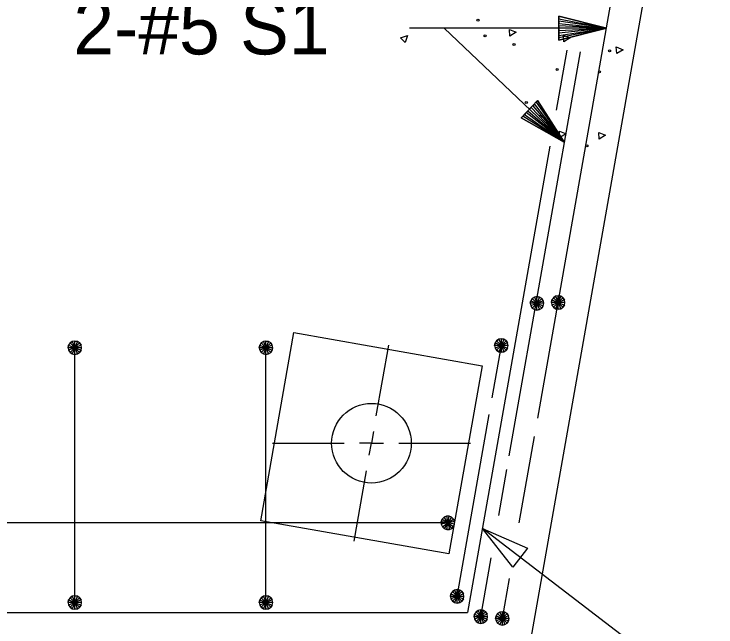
# Model space of a CAD drawing. Extents: x -408 to -23, y -15 to 117.
# Drawn here: x -81.977 to -80.141, y 60.353 to 61.957 of the extents above; entities that cross this region are included whole.
import ezdxf

# ---------------------------------------------------------------- set-up
doc = ezdxf.new("R2010")
doc.units = 0
for name, color, linetype in [('Arrowhead Terminators CELL', 7, 'Continuous'), ('Dimension Lines', 7, 'Continuous'), ('Rebar Lines', 7, 'Continuous'), ('Sup Concrete Girder Lines', 7, 'Continuous'), ('Sup Cored Slab Unit', 7, 'Continuous'), ('Text', 7, 'Continuous')]:
    doc.layers.add(name, color=color, linetype=linetype)

msp = doc.modelspace()

# ---------------------------------------------------------------- linework, layer by layer
at = {"layer": 'Arrowhead Terminators CELL'}
msp.add_lwpolyline([(-80.7517, 60.6104), (-80.6335, 60.5591), (-80.6716, 60.5095)], close=True, dxfattribs=at)
at = {"layer": 'Dimension Lines'}
for p, q in [((-80.4271, 61.9193), (-80.8512, 61.9194)), ((-81.0293, 60.9054), (-80.9967, 61.09)), ((-81.301, 60.8335), (-81.1135, 60.8335)), ((-80.9704, 60.8335), (-80.7829, 60.8335)), ((-81.0872, 60.5769), (-81.0546, 60.7615))]:
    msp.add_line(p, q, dxfattribs=at)
for points in [[(-80.5521, 61.9193), (-80.5521, 61.9131), (-80.4271, 61.9193), (-80.5521, 61.9068), (-80.5521, 61.9006), (-80.4271, 61.9193), (-80.5521, 61.8943), (-80.5521, 61.8881), (-80.4271, 61.9193), (-80.5521, 61.9506), (-80.5521, 61.9443), (-80.4271, 61.9193), (-80.5521, 61.9381), (-80.5521, 61.9318), (-80.4271, 61.9193), (-80.5521, 61.9256), (-80.5521, 61.8881), (-80.5521, 61.9506), (-80.4271, 61.9193), (-80.5521, 61.8881)], [(-80.5381, 61.6214), (-80.8512, 61.9194), (-80.9421, 61.9194)], [(-80.6287, 61.7076), (-80.633, 61.7031), (-80.5381, 61.6214), (-80.6373, 61.6985), (-80.6416, 61.694), (-80.5381, 61.6214), (-80.6459, 61.6895), (-80.6502, 61.685), (-80.5381, 61.6214), (-80.6071, 61.7302), (-80.6114, 61.7257), (-80.5381, 61.6214), (-80.6158, 61.7212), (-80.62, 61.7166), (-80.5381, 61.6214), (-80.6244, 61.7121), (-80.6502, 61.685), (-80.6071, 61.7302), (-80.5381, 61.6214), (-80.6502, 61.685)], [(-81.0365, 60.8644), (-81.0419, 60.8335), (-81.0734, 60.8336)], [(-81.0475, 60.8026), (-81.0419, 60.8335), (-81.0105, 60.8333)], [(-80.1546, 60.2743), (-80.3138, 60.2743), (-80.7517, 60.6104)]]:
    msp.add_lwpolyline(points, dxfattribs=at)
at = {"layer": 'Rebar Lines'}
for p, q in [((-80.4532, 61.7715), (-80.362, 62.2887)), ((-80.6815, 60.8001), (-80.4951, 61.8574)), ((-80.531, 61.8622), (-80.5587, 61.7052)), ((-80.6069, 60.8995), (-80.4532, 61.7715)), ((-80.5753, 61.611), (-80.7904, 60.3908)), ((-81.8177, 60.4168), (-81.8177, 61.0834)), ((-81.3177, 60.4168), (-81.3177, 61.0834)), ((-80.7262, 60.9519), (-80.702, 61.0893)), ((-80.8177, 60.4328), (-80.7338, 60.9087)), ((-80.6554, 60.6248), (-80.6154, 60.8515)), ((-80.709, 60.6441), (-80.6877, 60.7647)), ((-80.8419, 60.6251), (-83.5294, 60.6251)), ((-80.7556, 60.3796), (-80.7285, 60.5335)), ((-80.6994, 60.3751), (-80.681, 60.4791)), ((-82.1544, 60.3908), (-80.7904, 60.3908))]:
    msp.add_line(p, q, dxfattribs=at)
for points in [[(-80.5913, 61.1996), (-80.5926, 61.2063), (-80.5964, 61.2121), (-80.6021, 61.2159), (-80.6089, 61.2172), (-80.6156, 61.2159), (-80.6213, 61.2121), (-80.6251, 61.2064), (-80.6265, 61.1996), (-80.6251, 61.1929), (-80.6213, 61.1872), (-80.6157, 61.1833), (-80.6089, 61.182), (-80.6021, 61.1833), (-80.5964, 61.1871), (-80.5926, 61.1928), (-80.5913, 61.1996), (-80.6089, 61.1996), (-80.6265, 61.1996), (-80.6251, 61.2064), (-80.6089, 61.1996), (-80.6213, 61.2121), (-80.6156, 61.2159), (-80.6089, 61.1996), (-80.6089, 61.2172), (-80.6021, 61.2159), (-80.6089, 61.1996), (-80.5964, 61.2121), (-80.5926, 61.2063), (-80.6089, 61.1996), (-80.5926, 61.1928), (-80.5964, 61.1871), (-80.6089, 61.1996), (-80.6021, 61.1833), (-80.6089, 61.182), (-80.6089, 61.1996), (-80.6157, 61.1833), (-80.6213, 61.1872), (-80.6089, 61.1996), (-80.6251, 61.1929)], [(-80.536, 61.2018), (-80.5373, 61.2085), (-80.5411, 61.2142), (-80.5469, 61.2181), (-80.5536, 61.2194), (-80.5603, 61.2181), (-80.5661, 61.2142), (-80.5699, 61.2085), (-80.5712, 61.2018), (-80.5699, 61.195), (-80.5661, 61.1893), (-80.5604, 61.1855), (-80.5536, 61.1841), (-80.5469, 61.1855), (-80.5412, 61.1893), (-80.5373, 61.195), (-80.536, 61.2018), (-80.5536, 61.2018), (-80.5712, 61.2018), (-80.5699, 61.2085), (-80.5536, 61.2018), (-80.5661, 61.2142), (-80.5603, 61.2181), (-80.5536, 61.2018), (-80.5536, 61.2194), (-80.5469, 61.2181), (-80.5536, 61.2018), (-80.5411, 61.2142), (-80.5373, 61.2085), (-80.5536, 61.2018), (-80.5373, 61.195), (-80.5412, 61.1893), (-80.5536, 61.2018), (-80.5469, 61.1855), (-80.5536, 61.1841), (-80.5536, 61.2018), (-80.5604, 61.1855), (-80.5661, 61.1893), (-80.5536, 61.2018), (-80.5699, 61.195)], [(-81.8001, 61.0834), (-81.8014, 61.0901), (-81.8052, 61.0959), (-81.811, 61.0997), (-81.8177, 61.101), (-81.8245, 61.0997), (-81.8302, 61.0959), (-81.834, 61.0902), (-81.8353, 61.0834), (-81.834, 61.0767), (-81.8302, 61.071), (-81.8245, 61.0671), (-81.8177, 61.0658), (-81.811, 61.0671), (-81.8053, 61.0709), (-81.8014, 61.0766), (-81.8001, 61.0834), (-81.8177, 61.0834), (-81.8353, 61.0834), (-81.834, 61.0902), (-81.8177, 61.0834), (-81.8302, 61.0959), (-81.8245, 61.0997), (-81.8177, 61.0834), (-81.8177, 61.101), (-81.811, 61.0997), (-81.8177, 61.0834), (-81.8052, 61.0959), (-81.8014, 61.0901), (-81.8177, 61.0834), (-81.8014, 61.0766), (-81.8053, 61.0709), (-81.8177, 61.0834), (-81.811, 61.0671), (-81.8177, 61.0658), (-81.8177, 61.0834), (-81.8245, 61.0671), (-81.8302, 61.071), (-81.8177, 61.0834), (-81.834, 61.0767)], [(-81.3001, 61.0834), (-81.3014, 61.0901), (-81.3052, 61.0959), (-81.311, 61.0997), (-81.3177, 61.101), (-81.3245, 61.0997), (-81.3302, 61.0959), (-81.334, 61.0902), (-81.3353, 61.0834), (-81.334, 61.0767), (-81.3302, 61.071), (-81.3245, 61.0671), (-81.3177, 61.0658), (-81.311, 61.0671), (-81.3053, 61.0709), (-81.3014, 61.0766), (-81.3001, 61.0834), (-81.3177, 61.0834), (-81.3353, 61.0834), (-81.334, 61.0902), (-81.3177, 61.0834), (-81.3302, 61.0959), (-81.3245, 61.0997), (-81.3177, 61.0834), (-81.3177, 61.101), (-81.311, 61.0997), (-81.3177, 61.0834), (-81.3052, 61.0959), (-81.3014, 61.0901), (-81.3177, 61.0834), (-81.3014, 61.0766), (-81.3053, 61.0709), (-81.3177, 61.0834), (-81.311, 61.0671), (-81.3177, 61.0658), (-81.3177, 61.0834), (-81.3245, 61.0671), (-81.3302, 61.071), (-81.3177, 61.0834), (-81.334, 61.0767)], [(-80.6844, 61.0893), (-80.6857, 61.096), (-80.6895, 61.1017), (-80.6952, 61.1056), (-80.702, 61.1069), (-80.7087, 61.1056), (-80.7144, 61.1017), (-80.7182, 61.0961), (-80.7196, 61.0893), (-80.7182, 61.0826), (-80.7144, 61.0768), (-80.7087, 61.073), (-80.702, 61.0716), (-80.6952, 61.073), (-80.6895, 61.0768), (-80.6857, 61.0825), (-80.6844, 61.0893), (-80.702, 61.0893), (-80.7196, 61.0893), (-80.7182, 61.0961), (-80.702, 61.0893), (-80.7144, 61.1017), (-80.7087, 61.1056), (-80.702, 61.0893), (-80.702, 61.1069), (-80.6952, 61.1056), (-80.702, 61.0893), (-80.6895, 61.1017), (-80.6857, 61.096), (-80.702, 61.0893), (-80.6857, 61.0825), (-80.6895, 61.0768), (-80.702, 61.0893), (-80.6952, 61.073), (-80.702, 61.0716), (-80.702, 61.0893), (-80.7087, 61.073), (-80.7144, 61.0768), (-80.702, 61.0893), (-80.7182, 61.0826)], [(-80.8247, 60.6221), (-80.8248, 60.6289), (-80.8275, 60.6352), (-80.8325, 60.64), (-80.8389, 60.6425), (-80.8457, 60.6424), (-80.852, 60.6396), (-80.8568, 60.6346), (-80.8593, 60.6282), (-80.8591, 60.6213), (-80.8564, 60.615), (-80.8515, 60.6102), (-80.845, 60.6077), (-80.8381, 60.6079), (-80.8319, 60.6107), (-80.8271, 60.6157), (-80.8247, 60.6221), (-80.8419, 60.6251), (-80.8593, 60.6282), (-80.8568, 60.6346), (-80.8419, 60.6251), (-80.852, 60.6396), (-80.8457, 60.6424), (-80.8419, 60.6251), (-80.8389, 60.6425), (-80.8325, 60.64), (-80.8419, 60.6251), (-80.8275, 60.6352), (-80.8248, 60.6289), (-80.8419, 60.6251), (-80.8271, 60.6157), (-80.8319, 60.6107), (-80.8419, 60.6251), (-80.8381, 60.6079), (-80.845, 60.6077), (-80.8419, 60.6251), (-80.8515, 60.6102), (-80.8564, 60.615), (-80.8419, 60.6251), (-80.8591, 60.6213)], [(-80.8001, 60.4328), (-80.8014, 60.4395), (-80.8052, 60.4452), (-80.811, 60.4491), (-80.8177, 60.4504), (-80.8245, 60.4491), (-80.8302, 60.4452), (-80.834, 60.4396), (-80.8353, 60.4328), (-80.834, 60.4261), (-80.8302, 60.4203), (-80.8245, 60.4165), (-80.8177, 60.4151), (-80.811, 60.4165), (-80.8053, 60.4203), (-80.8014, 60.426), (-80.8001, 60.4328), (-80.8177, 60.4328), (-80.8353, 60.4328), (-80.834, 60.4396), (-80.8177, 60.4328), (-80.8302, 60.4452), (-80.8245, 60.4491), (-80.8177, 60.4328), (-80.8177, 60.4504), (-80.811, 60.4491), (-80.8177, 60.4328), (-80.8052, 60.4452), (-80.8014, 60.4395), (-80.8177, 60.4328), (-80.8014, 60.426), (-80.8053, 60.4203), (-80.8177, 60.4328), (-80.811, 60.4165), (-80.8177, 60.4151), (-80.8177, 60.4328), (-80.8245, 60.4165), (-80.8302, 60.4203), (-80.8177, 60.4328), (-80.834, 60.4261)], [(-81.8001, 60.4168), (-81.8014, 60.4235), (-81.8052, 60.4292), (-81.811, 60.4331), (-81.8177, 60.4344), (-81.8245, 60.4331), (-81.8302, 60.4292), (-81.834, 60.4235), (-81.8353, 60.4168), (-81.834, 60.41), (-81.8302, 60.4043), (-81.8245, 60.4005), (-81.8177, 60.3991), (-81.811, 60.4005), (-81.8053, 60.4043), (-81.8014, 60.41), (-81.8001, 60.4168), (-81.8177, 60.4168), (-81.8353, 60.4168), (-81.834, 60.4235), (-81.8177, 60.4168), (-81.8302, 60.4292), (-81.8245, 60.4331), (-81.8177, 60.4168), (-81.8177, 60.4344), (-81.811, 60.4331), (-81.8177, 60.4168), (-81.8052, 60.4292), (-81.8014, 60.4235), (-81.8177, 60.4168), (-81.8014, 60.41), (-81.8053, 60.4043), (-81.8177, 60.4168), (-81.811, 60.4005), (-81.8177, 60.3991), (-81.8177, 60.4168), (-81.8245, 60.4005), (-81.8302, 60.4043), (-81.8177, 60.4168), (-81.834, 60.41)], [(-81.3001, 60.4168), (-81.3014, 60.4235), (-81.3052, 60.4292), (-81.311, 60.4331), (-81.3177, 60.4344), (-81.3245, 60.4331), (-81.3302, 60.4292), (-81.334, 60.4235), (-81.3353, 60.4168), (-81.334, 60.41), (-81.3302, 60.4043), (-81.3245, 60.4005), (-81.3177, 60.3991), (-81.311, 60.4005), (-81.3053, 60.4043), (-81.3014, 60.41), (-81.3001, 60.4168), (-81.3177, 60.4168), (-81.3353, 60.4168), (-81.334, 60.4235), (-81.3177, 60.4168), (-81.3302, 60.4292), (-81.3245, 60.4331), (-81.3177, 60.4168), (-81.3177, 60.4344), (-81.311, 60.4331), (-81.3177, 60.4168), (-81.3052, 60.4292), (-81.3014, 60.4235), (-81.3177, 60.4168), (-81.3014, 60.41), (-81.3053, 60.4043), (-81.3177, 60.4168), (-81.311, 60.4005), (-81.3177, 60.3991), (-81.3177, 60.4168), (-81.3245, 60.4005), (-81.3302, 60.4043), (-81.3177, 60.4168), (-81.334, 60.41)], [(-80.738, 60.3796), (-80.7393, 60.3863), (-80.7431, 60.392), (-80.7488, 60.3959), (-80.7556, 60.3972), (-80.7623, 60.3959), (-80.7681, 60.392), (-80.7719, 60.3863), (-80.7732, 60.3796), (-80.7719, 60.3728), (-80.7681, 60.3671), (-80.7624, 60.3633), (-80.7556, 60.3619), (-80.7488, 60.3633), (-80.7432, 60.3671), (-80.7393, 60.3728), (-80.738, 60.3796), (-80.7556, 60.3796), (-80.7732, 60.3796), (-80.7719, 60.3863), (-80.7556, 60.3796), (-80.7681, 60.392), (-80.7623, 60.3959), (-80.7556, 60.3796), (-80.7556, 60.3972), (-80.7488, 60.3959), (-80.7556, 60.3796), (-80.7431, 60.392), (-80.7393, 60.3863), (-80.7556, 60.3796), (-80.7393, 60.3728), (-80.7432, 60.3671), (-80.7556, 60.3796), (-80.7488, 60.3633), (-80.7556, 60.3619), (-80.7556, 60.3796), (-80.7624, 60.3633), (-80.7681, 60.3671), (-80.7556, 60.3796), (-80.7719, 60.3728)], [(-80.6818, 60.3751), (-80.6831, 60.3819), (-80.6869, 60.3876), (-80.6926, 60.3914), (-80.6994, 60.3927), (-80.7061, 60.3914), (-80.7118, 60.3876), (-80.7156, 60.3819), (-80.717, 60.3751), (-80.7156, 60.3684), (-80.7118, 60.3627), (-80.7061, 60.3588), (-80.6994, 60.3575), (-80.6926, 60.3588), (-80.6869, 60.3626), (-80.6831, 60.3684), (-80.6818, 60.3751), (-80.6994, 60.3751), (-80.717, 60.3751), (-80.7156, 60.3819), (-80.6994, 60.3751), (-80.7118, 60.3876), (-80.7061, 60.3914), (-80.6994, 60.3751), (-80.6994, 60.3927), (-80.6926, 60.3914), (-80.6994, 60.3751), (-80.6869, 60.3876), (-80.6831, 60.3819), (-80.6994, 60.3751), (-80.6831, 60.3684), (-80.6869, 60.3626), (-80.6994, 60.3751), (-80.6926, 60.3588), (-80.6994, 60.3575), (-80.6994, 60.3751), (-80.7061, 60.3588), (-80.7118, 60.3627), (-80.6994, 60.3751), (-80.7156, 60.3684)]]:
    msp.add_lwpolyline(points, dxfattribs=at)
at = {"layer": 'Sup Concrete Girder Lines'}
msp.add_line((-80.6589, 60.1251), (-80.1408, 63.0636), dxfattribs=at)
for points in [[(-80.6797, 61.8987), (-80.6811, 61.916), (-80.6632, 61.9088), (-80.6797, 61.8987)], [(-80.9539, 61.8818), (-80.9662, 61.8941), (-80.9478, 61.9002), (-80.9539, 61.8818)], [(-80.5383, 61.8842), (-80.5398, 61.9014), (-80.5218, 61.8943), (-80.5383, 61.8842)], [(-80.4002, 61.8532), (-80.4017, 61.8704), (-80.3837, 61.8633), (-80.4002, 61.8532)], [(-80.5488, 61.6331), (-80.5503, 61.6503), (-80.5323, 61.6432), (-80.5488, 61.6331)], [(-80.4458, 61.6291), (-80.4472, 61.6464), (-80.4293, 61.6393), (-80.4458, 61.6291)]]:
    msp.add_lwpolyline(points, dxfattribs=at)
for centre, radius in [((-80.7632, 61.9403), 0.00273), ((-80.7447, 61.8993), 0.00273), ((-80.6689, 61.8768), 0.00273), ((-80.4189, 61.8604), 0.00273), ((-80.5562, 61.8112), 0.00273), ((-80.4456, 61.8051), 0.00273), ((-80.6368, 61.7249), 0.00273), ((-80.5992, 61.6892), 0.00273), ((-80.4782, 61.6119), 0.00273), ((-81.0419, 60.8335), 0.1042)]:
    msp.add_circle(centre, radius, dxfattribs=at)
at = {"layer": 'Sup Cored Slab Unit'}
msp.add_lwpolyline([(-81.2447, 61.1231), (-80.7523, 61.0363), (-80.8391, 60.5439), (-81.3315, 60.6307)], close=True, dxfattribs=at)

# ---------------------------------------------------------------- texts
at = {"layer": 'Text'}
msp.add_text('2-#5 S1', height=0.14302, dxfattribs=at).set_placement((-81.8214, 61.8509))

doc.saveas('drawing.dxf')
